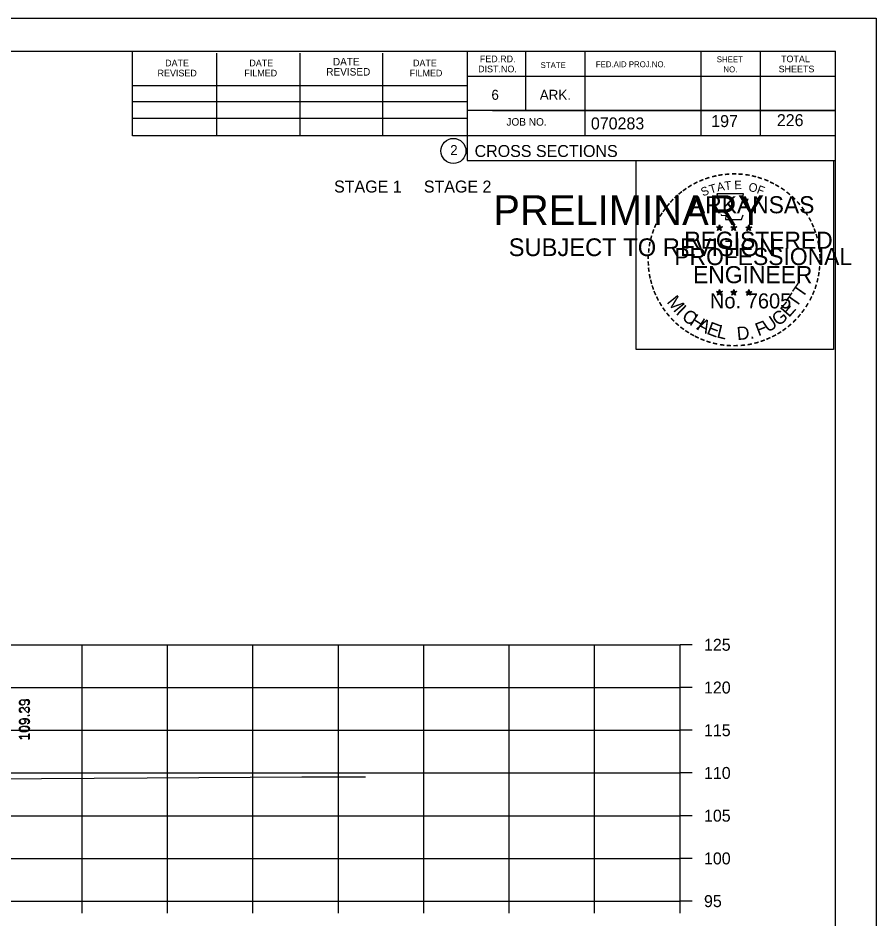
# Model space of a CAD drawing. Extents: x 1175611 to 1176402, y -433344 to -416213.
# Drawn here: x 1175843.5 to 1175943.9, y -422568.7 to -422463.3 of the extents above; entities that cross this region are included whole.
import ezdxf

# ---------------------------------------------------------------- set-up
doc = ezdxf.new("R2010")
doc.units = 0
for name, color, linetype in [('Default', 7, 'Continuous'), ('R_Axis', 7, 'Continuous'), ('R_Axis Annot', 7, 'Continuous'), ('R_Border', 7, 'Continuous'), ('R_Border Notes', 7, 'Continuous'), ('R_Border PE', 7, 'Continuous'), ('R_Border Prem', 7, 'Continuous'), ('R_Exist Surface', 7, 'Continuous'), ('R_Grid', 7, 'Continuous'), ('R_No Plot', 7, 'Continuous'), ('R_Xsect Elev', 7, 'Continuous')]:
    doc.layers.add(name, color=color, linetype=linetype)

msp = doc.modelspace()

# ---------------------------------------------------------------- linework, layer by layer
at = {"layer": 'R_Axis'}
for p, q in [((1175920.97, -422566.65), (1175920.97, -422536.65)), ((1175922.37, -422536.65), (1175920.97, -422536.65)), ((1175922.37, -422541.65), (1175920.97, -422541.65)), ((1175922.37, -422546.65), (1175920.97, -422546.65)), ((1175922.37, -422551.65), (1175920.97, -422551.65)), ((1175922.37, -422556.65), (1175920.97, -422556.65)), ((1175922.37, -422561.65), (1175920.97, -422561.65)), ((1175640.97, -422566.65), (1175920.97, -422566.65)), ((1175850.97, -422568.05), (1175850.97, -422566.65)), ((1175860.97, -422568.05), (1175860.97, -422566.65)), ((1175870.97, -422568.05), (1175870.97, -422566.65)), ((1175880.97, -422568.05), (1175880.97, -422566.65)), ((1175890.97, -422568.05), (1175890.97, -422566.65)), ((1175900.97, -422568.05), (1175900.97, -422566.65)), ((1175910.97, -422568.05), (1175910.97, -422566.65)), ((1175920.97, -422568.05), (1175920.97, -422566.65)), ((1175922.37, -422566.65), (1175920.97, -422566.65))]:
    msp.add_line(p, q, dxfattribs=at)
at = {"layer": 'R_Border'}
for p, q in [((1175622.97, -422467.19), (1175939.15, -422467.19)), ((1175856.89, -422477.07), (1175856.89, -422467.19)), ((1175866.75, -422477.07), (1175866.75, -422467.39)), ((1175876.51, -422477.07), (1175876.51, -422467.39)), ((1175886.19, -422477.07), (1175886.19, -422467.39)), ((1175896.05, -422467.19), (1175896.05, -422479.99)), ((1175902.89, -422467.19), (1175902.89, -422474.13)), ((1175909.83, -422467.19), (1175909.83, -422477.07)), ((1175923.41, -422467.19), (1175923.41, -422477.07)), ((1175930.35, -422467.19), (1175930.35, -422477.07)), ((1175939.15, -422672.65), (1175939.15, -422467.19)), ((1175939.15, -422470.13), (1175896.05, -422470.13)), ((1175939.15, -422470.11), (1175939.15, -422470.11)), ((1175856.89, -422471.21), (1175896.05, -422471.21)), ((1175856.89, -422473.07), (1175896.05, -422473.07)), ((1175939.15, -422474.13), (1175896.05, -422474.13)), ((1175899.01, -422474.13), (1175939.15, -422474.13)), ((1175856.89, -422477.07), (1175856.89, -422475.01)), ((1175856.89, -422475.01), (1175896.05, -422475.01)), ((1175939.15, -422477.07), (1175856.89, -422477.07)), ((1175896.05, -422479.99), (1175939.15, -422479.99))]:
    msp.add_line(p, q, dxfattribs=at)
msp.add_circle((1175894.44, -422478.85), 1.47, dxfattribs=at)
at = {"layer": 'R_Border PE'}
for p, q in [((1175925.58, -422487.49), (1175925.54, -422487.74)), ((1175925.58, -422487.85), (1175925.58, -422487.49)), ((1175925.58, -422487.49), (1175925.63, -422487.74)), ((1175927.25, -422487.49), (1175927.21, -422487.74)), ((1175927.25, -422487.85), (1175927.25, -422487.49)), ((1175927.25, -422487.49), (1175927.3, -422487.74)), ((1175929.02, -422487.5), (1175928.98, -422487.75)), ((1175929.02, -422487.87), (1175929.02, -422487.5)), ((1175929.02, -422487.5), (1175929.07, -422487.75)), ((1175925.23, -422487.74), (1175925.58, -422487.85)), ((1175925.23, -422487.74), (1175925.49, -422487.79)), ((1175925.23, -422487.74), (1175925.47, -422487.87)), ((1175925.37, -422488.15), (1175925.58, -422487.85)), ((1175925.37, -422488.15), (1175925.49, -422487.91)), ((1175925.37, -422488.15), (1175925.58, -422487.93)), ((1175925.93, -422487.74), (1175925.58, -422487.85)), ((1175925.8, -422488.15), (1175925.58, -422487.85)), ((1175925.8, -422488.15), (1175925.58, -422487.94)), ((1175925.93, -422487.74), (1175925.64, -422487.79)), ((1175925.8, -422488.15), (1175925.66, -422487.86)), ((1175925.93, -422487.74), (1175925.73, -422487.85)), ((1175926.9, -422487.74), (1175927.25, -422487.85)), ((1175926.9, -422487.74), (1175927.16, -422487.79)), ((1175926.9, -422487.74), (1175927.14, -422487.87)), ((1175927.04, -422488.15), (1175927.25, -422487.85)), ((1175927.04, -422488.15), (1175927.16, -422487.91)), ((1175927.04, -422488.15), (1175927.25, -422487.93)), ((1175927.6, -422487.74), (1175927.25, -422487.85)), ((1175927.47, -422488.15), (1175927.25, -422487.85)), ((1175927.47, -422488.15), (1175927.25, -422487.94)), ((1175927.6, -422487.74), (1175927.31, -422487.79)), ((1175927.47, -422488.15), (1175927.33, -422487.86)), ((1175927.6, -422487.74), (1175927.4, -422487.85)), ((1175928.67, -422487.76), (1175929.02, -422487.87)), ((1175928.67, -422487.76), (1175928.92, -422487.8)), ((1175928.67, -422487.76), (1175928.91, -422487.88)), ((1175928.8, -422488.16), (1175929.02, -422487.87)), ((1175928.8, -422488.16), (1175928.93, -422487.92)), ((1175928.8, -422488.16), (1175929.02, -422487.95)), ((1175929.36, -422487.76), (1175929.02, -422487.87)), ((1175929.23, -422488.16), (1175929.02, -422487.87)), ((1175929.23, -422488.16), (1175929.02, -422487.95)), ((1175929.36, -422487.76), (1175929.08, -422487.8)), ((1175929.23, -422488.16), (1175929.09, -422487.87)), ((1175929.36, -422487.76), (1175929.16, -422487.86)), ((1175925.23, -422495.32), (1175925.58, -422495.43)), ((1175925.23, -422495.32), (1175925.48, -422495.36)), ((1175925.23, -422495.32), (1175925.47, -422495.44)), ((1175925.36, -422495.72), (1175925.58, -422495.43)), ((1175925.36, -422495.72), (1175925.49, -422495.48)), ((1175925.36, -422495.72), (1175925.58, -422495.51)), ((1175925.58, -422495.06), (1175925.54, -422495.31)), ((1175925.58, -422495.43), (1175925.58, -422495.06)), ((1175925.58, -422495.06), (1175925.63, -422495.31)), ((1175925.93, -422495.32), (1175925.58, -422495.43)), ((1175925.79, -422495.72), (1175925.58, -422495.43)), ((1175925.79, -422495.72), (1175925.58, -422495.51)), ((1175925.93, -422495.32), (1175925.64, -422495.37)), ((1175925.79, -422495.72), (1175925.66, -422495.43)), ((1175925.93, -422495.32), (1175925.72, -422495.42)), ((1175926.9, -422495.32), (1175927.25, -422495.43)), ((1175926.9, -422495.32), (1175927.15, -422495.36)), ((1175926.9, -422495.32), (1175927.14, -422495.44)), ((1175927.03, -422495.72), (1175927.25, -422495.43)), ((1175927.03, -422495.72), (1175927.16, -422495.48)), ((1175927.03, -422495.72), (1175927.25, -422495.51)), ((1175927.25, -422495.06), (1175927.21, -422495.31)), ((1175927.25, -422495.43), (1175927.25, -422495.06)), ((1175927.25, -422495.06), (1175927.3, -422495.31)), ((1175927.6, -422495.32), (1175927.25, -422495.43)), ((1175927.46, -422495.72), (1175927.25, -422495.43)), ((1175927.46, -422495.72), (1175927.25, -422495.51)), ((1175927.6, -422495.32), (1175927.31, -422495.37)), ((1175927.46, -422495.72), (1175927.32, -422495.43)), ((1175927.6, -422495.32), (1175927.39, -422495.42)), ((1175928.67, -422495.33), (1175929.02, -422495.44)), ((1175928.67, -422495.33), (1175928.92, -422495.37)), ((1175928.67, -422495.33), (1175928.9, -422495.45)), ((1175928.8, -422495.73), (1175929.02, -422495.44)), ((1175928.8, -422495.73), (1175928.93, -422495.49)), ((1175928.8, -422495.73), (1175929.01, -422495.52)), ((1175929.02, -422495.07), (1175928.97, -422495.32)), ((1175929.23, -422495.73), (1175929.01, -422495.52)), ((1175929.02, -422495.44), (1175929.02, -422495.07)), ((1175929.02, -422495.07), (1175929.06, -422495.32)), ((1175929.36, -422495.33), (1175929.02, -422495.44)), ((1175929.23, -422495.73), (1175929.02, -422495.44)), ((1175929.36, -422495.33), (1175929.08, -422495.38)), ((1175929.23, -422495.73), (1175929.09, -422495.44)), ((1175929.36, -422495.33), (1175929.16, -422495.43))]:
    msp.add_line(p, q, dxfattribs=at)
for points in [[(1175925.28, -422483.87), (1175925.54, -422484.69)], [(1175928.79, -422484.79), (1175928.93, -422484.5), (1175928.24, -422484.53), (1175928.39, -422483.87), (1175925.28, -422483.87)], [(1175925.77, -422486.29), (1175925.77, -422486.38), (1175926.33, -422486.39), (1175926.28, -422486.87), (1175928.15, -422486.87), (1175928.35, -422486.33)], [(1175925.58, -422487.49), (1175925.8, -422488.15), (1175925.23, -422487.74), (1175925.93, -422487.74), (1175925.37, -422488.15), (1175925.58, -422487.49)], [(1175927.25, -422487.49), (1175927.47, -422488.15), (1175926.9, -422487.74), (1175927.6, -422487.74), (1175927.04, -422488.15), (1175927.25, -422487.49)], [(1175929.02, -422487.5), (1175929.23, -422488.16), (1175928.67, -422487.76), (1175929.36, -422487.76), (1175928.8, -422488.16), (1175929.02, -422487.5)], [(1175925.58, -422495.06), (1175925.79, -422495.72), (1175925.23, -422495.32), (1175925.93, -422495.32), (1175925.36, -422495.72), (1175925.58, -422495.06)], [(1175927.25, -422495.06), (1175927.46, -422495.72), (1175926.9, -422495.32), (1175927.6, -422495.32), (1175927.03, -422495.72), (1175927.25, -422495.06)], [(1175929.02, -422495.07), (1175929.23, -422495.73), (1175928.67, -422495.33), (1175929.36, -422495.33), (1175928.8, -422495.73), (1175929.02, -422495.07)]]:
    msp.add_lwpolyline(points, dxfattribs=at)
for centre, radius in [((1175925.58, -422487.86), 0.172), ((1175925.58, -422487.86), 0.145), ((1175925.58, -422487.86), 0.116), ((1175925.58, -422487.86), 0.0991), ((1175925.58, -422487.86), 0.0747), ((1175925.58, -422487.86), 0.0495), ((1175925.58, -422487.86), 0.0296), ((1175927.25, -422487.86), 0.172), ((1175927.25, -422487.86), 0.145), ((1175927.25, -422487.86), 0.116), ((1175927.25, -422487.86), 0.0991), ((1175927.25, -422487.86), 0.0747), ((1175927.25, -422487.86), 0.0495), ((1175927.25, -422487.86), 0.0296), ((1175929.02, -422487.87), 0.172), ((1175929.02, -422487.87), 0.145), ((1175929.02, -422487.87), 0.116), ((1175929.02, -422487.87), 0.0991), ((1175929.02, -422487.87), 0.0747), ((1175929.02, -422487.87), 0.0495), ((1175929.02, -422487.87), 0.0296), ((1175925.58, -422495.43), 0.172), ((1175925.58, -422495.43), 0.145), ((1175925.58, -422495.43), 0.116), ((1175925.58, -422495.43), 0.0991), ((1175925.58, -422495.43), 0.0747), ((1175925.58, -422495.43), 0.0495), ((1175925.58, -422495.43), 0.0296), ((1175927.25, -422495.43), 0.172), ((1175927.25, -422495.43), 0.145), ((1175927.25, -422495.43), 0.116), ((1175927.25, -422495.43), 0.0991), ((1175927.25, -422495.43), 0.0747), ((1175927.25, -422495.43), 0.0495), ((1175927.25, -422495.43), 0.0296), ((1175929.01, -422495.44), 0.172), ((1175929.01, -422495.44), 0.145), ((1175929.01, -422495.44), 0.116), ((1175929.01, -422495.44), 0.0991), ((1175929.01, -422495.44), 0.0747), ((1175929.01, -422495.44), 0.0495), ((1175929.01, -422495.44), 0.0296)]:
    msp.add_circle(centre, radius, dxfattribs=at)
at = {"layer": 'R_Exist Surface'}
msp.add_lwpolyline([(1175839.96, -422552.33), (1175858.57, -422552.22), (1175876.69, -422552.1), (1175878.21, -422552.1), (1175884.14, -422552.1)], dxfattribs=at)
at = {"layer": 'R_Grid'}
for p, q in [((1175640.97, -422536.65), (1175920.97, -422536.65)), ((1175850.97, -422566.65), (1175850.97, -422536.65)), ((1175860.97, -422566.65), (1175860.97, -422536.65)), ((1175870.97, -422566.65), (1175870.97, -422536.65)), ((1175880.97, -422566.65), (1175880.97, -422536.65)), ((1175890.97, -422566.65), (1175890.97, -422536.65)), ((1175900.97, -422566.65), (1175900.97, -422536.65)), ((1175910.97, -422566.65), (1175910.97, -422536.65)), ((1175920.97, -422566.65), (1175920.97, -422536.65)), ((1175640.97, -422541.65), (1175920.97, -422541.65)), ((1175640.97, -422546.65), (1175920.97, -422546.65)), ((1175640.97, -422551.65), (1175920.97, -422551.65)), ((1175640.97, -422556.65), (1175920.97, -422556.65)), ((1175640.97, -422561.65), (1175920.97, -422561.65)), ((1175640.97, -422566.65), (1175920.97, -422566.65))]:
    msp.add_line(p, q, dxfattribs=at)
at = {"layer": 'R_No Plot'}
msp.add_line((1175610.57, -422463.3), (1175943.91, -422463.3), dxfattribs=at)
for points in [[(1175610.57, -422463.3), (1175943.91, -422463.3), (1175943.91, -422676.63), (1175610.57, -422676.63)], [(1175915.82, -422479.96), (1175938.92, -422479.96), (1175938.92, -422502.11), (1175915.82, -422502.11)]]:
    msp.add_lwpolyline(points, close=True, dxfattribs=at)

# ---------------------------------------------------------------- texts
at = {"layer": 'Default'}
msp.add_text('STAGE 1     STAGE 2', height=1.4, dxfattribs=at).set_placement((1175880.47, -422483.72))
at = {"layer": 'R_Axis Annot'}
for s, p in [('125', (1175923.77, -422537.35)), ('120', (1175923.77, -422542.35)), ('115', (1175923.77, -422547.35)), ('110', (1175923.77, -422552.35)), ('105', (1175923.77, -422557.35)), ('100', (1175923.77, -422562.35)), ('95', (1175923.77, -422567.35))]:
    msp.add_text(s, height=1.4, dxfattribs=at).set_placement(p)
at = {"layer": 'R_Border'}
for s, height, p in [('DATE', 0.782, (1175860.69, -422468.95)), ('DATE', 0.782, (1175870.55, -422468.95)), ('DATE', 0.879, (1175880.33, -422468.85)), ('DATE', 0.782, (1175889.71, -422468.95)), ('FED.RD.', 0.782, (1175897.53, -422468.47)), ('STATE', 0.684, (1175904.65, -422469.15)), ('FED.AID PROJ.NO.', 0.684, (1175911.11, -422469.05)), ('SHEET', 0.684, (1175925.27, -422468.47)), ('TOTAL', 0.782, (1175932.79, -422468.47)), ('REVISED', 0.782, (1175859.81, -422470.13)), ('FILMED', 0.782, (1175869.97, -422470.13)), ('REVISED', 0.879, (1175879.55, -422470.03)), ('FILMED', 0.782, (1175889.31, -422470.13)), ('DIST.NO.', 0.782, (1175897.33, -422469.65)), ('NO.', 0.684, (1175926.05, -422469.65)), ('SHEETS', 0.782, (1175932.51, -422469.65)), ('6', 1.17, (1175898.89, -422472.87)), ('ARK.', 1.172, (1175904.55, -422472.87)), ('070283', 1.4, (1175910.53, -422476.33)), ('JOB NO.', 0.879, (1175900.65, -422475.89)), ('2', 1.17, (1175894.06, -422479.34)), ('CROSS SECTIONS', 1.4, (1175896.92, -422479.56))]:
    msp.add_text(s, height=height, rotation=360, dxfattribs=at).set_placement(p)
at = {"layer": 'R_Border Notes'}
for s, p in [('197', (1175924.62, -422476.06)), ('226', (1175932.3, -422475.95))]:
    msp.add_text(s, height=1.4, dxfattribs=at).set_placement(p)
at = {"layer": 'R_Border PE'}
for s, height, rotation, p in [('-', 1.6, 24.3072, (1175923.39, -422483.01)), ('-', 1.6, 19.1761, (1175924.02, -422482.74)), ('-', 1.6, 13.6301, (1175924.77, -422482.5)), ('-', 1.6, 10.2193, (1175925.45, -422482.34)), ('-', 1.6, 5.8968, (1175926.18, -422482.23)), ('-', 1.6, 0.1862, (1175926.95, -422482.15)), ('E', 1, 0.8323, (1175927.32, -422483.33)), ('-', 1.6, 357.743, (1175927.67, -422482.17)), ('-', 1.6, 352.1617, (1175928.42, -422482.22)), ('-', 1.6, 347.2049, (1175929.14, -422482.34)), ('-', 1.6, 342.3362, (1175929.77, -422482.49)), ('-', 1.6, 337.8551, (1175930.51, -422482.71)), ('-', 1.6, 36.2317, (1175921.58, -422484.09)), ('-', 1.6, 34.0636, (1175922.16, -422483.69)), ('-', 1.6, 28.7918, (1175922.76, -422483.32)), ('S', 1, 21.594, (1175923.63, -422484.19)), ('T', 1, 16.4036, (1175924.54, -422483.86)), ('A', 1, 11.2132, (1175925.37, -422483.61)), ('T', 1, 6.0228, (1175926.22, -422483.44)), ('O', 1, 350.4515, (1175928.93, -422483.54)), ('F', 1, 340.0707, (1175929.88, -422483.77)), ('-', 1.6, 334.1211, (1175931.14, -422482.99)), ('-', 1.6, 329.6409, (1175931.72, -422483.27)), ('-', 1.6, 325.8627, (1175932.36, -422483.63)), ('-', 1.6, 48.423, (1175920.22, -422485.36)), ('-', 1.6, 42.9622, (1175920.67, -422484.88)), ('-', 1.6, 38.9507, (1175921.1, -422484.47)), ('ARKANSAS', 2, 360, (1175922.13, -422486.15)), ('-', 1.6, 320.5297, (1175932.97, -422484.06)), ('-', 1.6, 315.5786, (1175933.57, -422484.54)), ('-', 1.6, 50.6142, (1175919.82, -422485.85)), ('-', 1.6, 309.8797, (1175934.14, -422485.09)), ('-', 1.6, 306.6522, (1175934.66, -422485.7)), ('-', 1.6, 58.0706, (1175919.08, -422486.94)), ('-', 1.6, 54.2325, (1175919.41, -422486.42)), ('-', 1.4, 303.6753, (1175935.15, -422486.26)), ('-', 1.6, 67.7743, (1175918.51, -422488.17)), ('-', 1.6, 62.8713, (1175918.77, -422487.56)), ('-', 1.6, 299.6684, (1175935.47, -422486.87)), ('-', 1.6, 294.6628, (1175935.79, -422487.48)), ('-', 1.6, 72.3945, (1175918.29, -422488.8)), ('REGISTERED', 2, 360, (1175921.45, -422490.3)), ('DWB', 0.01, 360, (1175925.57, -422487.86)), ('DWB', 0.01, 360, (1175927.24, -422487.86)), ('DWB', 0.01, 360, (1175929, -422487.87)), ('-', 1.6, 290.5728, (1175936.05, -422488.06)), ('-', 1.6, 285.1233, (1175936.28, -422488.64)), ('-', 1.6, 81.2013, (1175917.96, -422490.22)), ('-', 1.6, 75.461, (1175918.09, -422489.51)), ('-', 1.6, 280.5493, (1175936.48, -422489.38)), ('-', 1.6, 85.1863, (1175917.89, -422490.92)), ('PROFESSIONAL', 2, 360, (1175920.3, -422492.21)), ('-', 1.6, 276.5962, (1175936.65, -422490.15)), ('-', 1.6, 94.1959, (1175917.9, -422492.34)), ('-', 1.6, 89.0622, (1175917.86, -422491.62)), ('-', 1.6, 274.3301, (1175936.71, -422490.87)), ('-', 1.6, 269.9407, (1175936.74, -422491.5)), ('-', 1.6, 98.9479, (1175917.97, -422493.01)), ('ENGINEER', 2, 360, (1175922.49, -422494.33)), ('-', 1.6, 263.5172, (1175936.72, -422492.17)), ('-', 1.6, 101.7149, (1175918.1, -422493.74)), ('-', 1.6, 105.4578, (1175918.27, -422494.34)), ('-', 1.6, 255.7626, (1175936.54, -422493.5)), ('-', 1.6, 260.9953, (1175936.65, -422492.82)), ('-', 1.6, 109.0874, (1175918.48, -422494.97)), ('T', 1.54, 55.055, (1175935.3, -422496.16)), ('-', 1.6, 252.8681, (1175936.36, -422494.22)), ('-', 1.6, 114.0643, (1175918.73, -422495.56)), ('-', 1.6, 115.7289, (1175919.04, -422496.18)), ('M', 1.54, 308.9175, (1175919.35, -422496.54)), ('No. 7605', 1.757, 360, (1175924.46, -422497.28)), ('DWB', 0.01, 360, (1175925.56, -422495.43)), ('DWB', 0.01, 360, (1175927.23, -422495.43)), ('DWB', 0.01, 360, (1175929, -422495.44)), ('T', 1.54, 55.055, (1175934.57, -422497.28)), ('-', 1.6, 244.6197, (1175935.87, -422495.52)), ('-', 1.6, 247.8887, (1175936.14, -422494.89)), ('-', 1.6, 120.4471, (1175919.4, -422496.77)), ('I', 1.54, 316.4636, (1175920.39, -422497.86)), ('E', 1.54, 48.7313, (1175933.72, -422498.41)), ('-', 1.6, 239.0712, (1175935.48, -422496.28)), ('-', 1.6, 125.8934, (1175919.8, -422497.33)), ('-', 1.6, 130.7181, (1175920.26, -422497.88)), ('C', 1.54, 324.0197, (1175921.06, -422498.48)), ('H', 1.54, 327.5342, (1175921.97, -422499.14)), ('U', 1.54, 34.4052, (1175931.27, -422500.16)), ('G', 1.54, 38.2173, (1175932.47, -422499.43)), ('-', 1.6, 231.2538, (1175934.65, -422497.49)), ('-', 1.6, 233.8452, (1175935.08, -422496.93)), ('-', 1.6, 134.2238, (1175920.78, -422498.43)), ('-', 1.6, 138.9338, (1175921.3, -422498.89)), ('A', 1.54, 332.5513, (1175922.83, -422499.67)), ('E', 1.54, 339.2068, (1175923.99, -422500.23)), ('F', 1.54, 20.8202, (1175930.13, -422500.56)), ('-', 1.6, 221.0851, (1175933.65, -422498.57)), ('-', 1.6, 225.7653, (1175934.17, -422498.06)), ('-', 1.6, 144.6463, (1175921.86, -422499.3)), ('-', 1.6, 148.0898, (1175922.42, -422499.67)), ('-', 1.6, 151.5704, (1175923, -422499.99)), ('L', 1.54, 346.2929, (1175925.18, -422500.66)), ('D.', 1.54, 5.2602, (1175927.68, -422501)), ('-', 1.6, 212.2491, (1175932.56, -422499.43)), ('-', 1.6, 215.7363, (1175933.1, -422499.04)), ('-', 1.6, 154.6002, (1175923.52, -422500.24)), ('-', 1.6, 158.5612, (1175924.15, -422500.49)), ('-', 1.6, 162.7983, (1175924.83, -422500.71)), ('-', 1.6, 167.5555, (1175925.55, -422500.87)), ('-', 1.6, 195.4743, (1175930.09, -422500.61)), ('-', 1.6, 200.7184, (1175930.76, -422500.36)), ('-', 1.6, 204.2516, (1175931.38, -422500.09)), ('-', 1.6, 207.3568, (1175932.01, -422499.77)), ('-', 1.6, 173.1155, (1175926.32, -422500.98)), ('-', 1.6, 176.5183, (1175927.07, -422501.03)), ('-', 1.6, 181.5918, (1175927.81, -422501.01)), ('-', 1.6, 185.8167, (1175928.62, -422500.94)), ('-', 1.6, 191.2858, (1175929.36, -422500.81))]:
    msp.add_text(s, height=height, rotation=rotation, dxfattribs=at).set_placement(p)
at = {"layer": 'R_Border Prem'}
for s, height, p in [('PRELIMINARY', 3.5, (1175899.1, -422487.53)), ('DWB', 0.01, (1175899.85, -422485.68)), ('SUBJECT TO REVISION', 2.0751, (1175900.91, -422491.16))]:
    msp.add_text(s, height=height, rotation=360, dxfattribs=at).set_placement(p)
at = {"layer": 'R_Xsect Elev'}
for s, p in [('109.29', (1175844.76, -422547.86)), ('109.33', (1175844.88, -422547.82))]:
    msp.add_text(s, height=1.2, rotation=90, dxfattribs=at).set_placement(p)

doc.saveas('drawing.dxf')
